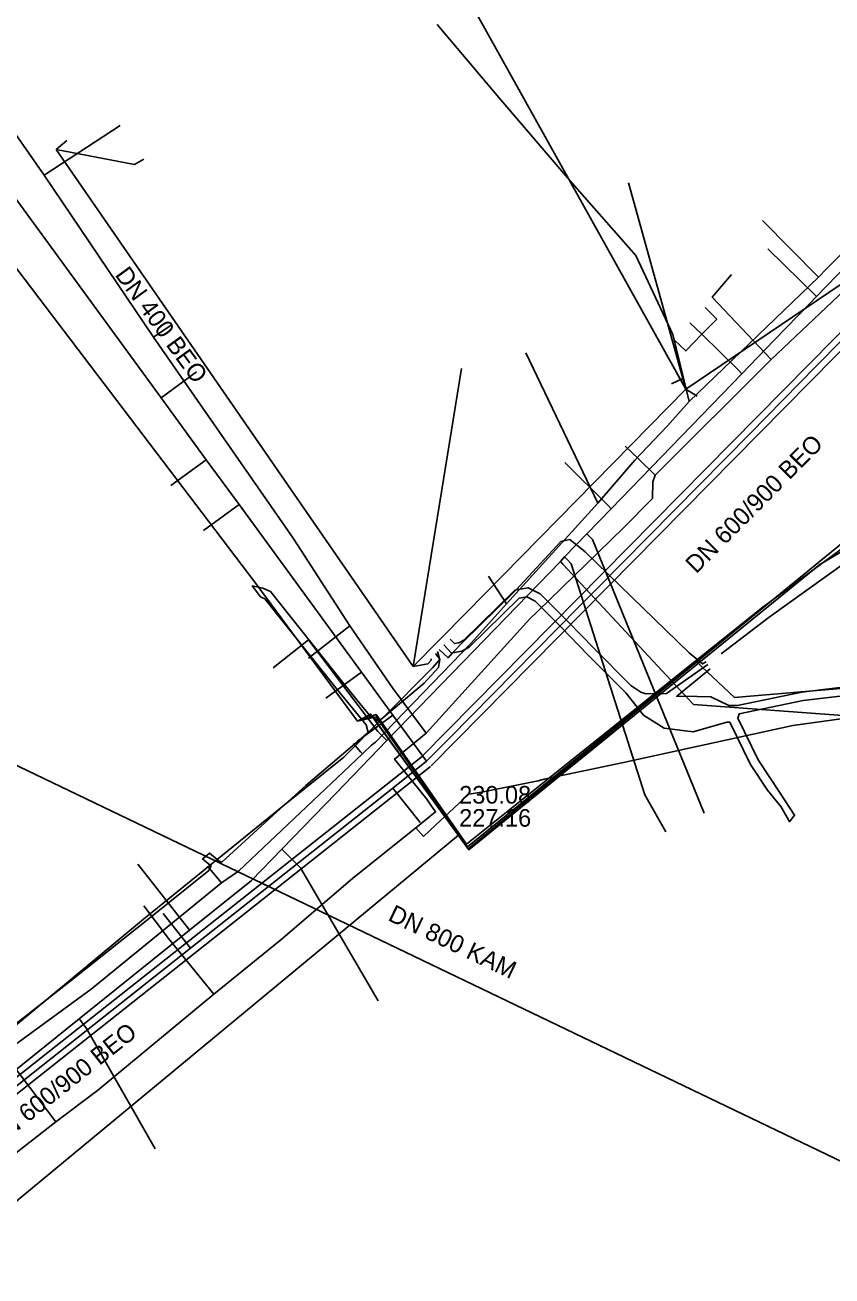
# Model space of a CAD drawing. Extents: x -598233 to -596890, y -1157848 to -1156431.
# Drawn here: x -597360.2 to -597323.5, y -1157480.1 to -1157423.2 of the extents above; entities that cross this region are included whole.
import ezdxf

# ---------------------------------------------------------------- set-up
doc = ezdxf.new("R2010")
doc.units = 0
for name, color, linetype in [('Vrstva 10', 7, 'Continuous'), ('Vrstva 12', 7, 'Continuous'), ('Vrstva 13', 7, 'Continuous'), ('Vrstva 16', 7, 'Continuous'), ('Vrstva 42', 7, 'Continuous'), ('Vrstva 5', 7, 'Continuous'), ('Vrstva 51', 7, 'Continuous'), ('Vrstva 55', 7, 'Continuous'), ('Vrstva 8', 7, 'Continuous'), ('Vrstva 9', 7, 'Continuous')]:
    doc.layers.add(name, color=color, linetype=linetype)

msp = doc.modelspace()

# ---------------------------------------------------------------- linework, layer by layer
at = {"layer": 'Vrstva 10'}
for p, q in [((-597310.498, -1157424.423), (-597342.123, -1157456.459)), ((-597310.072, -1157424.845), (-597341.697, -1157456.881)), ((-597342.096, -1157456.435), (-597369.306, -1157477.955)), ((-597341.724, -1157456.905), (-597368.934, -1157478.425))]:
    msp.add_line(p, q, dxfattribs=at)
at = {"layer": 'Vrstva 12'}
for points in [[(-597330.23, -1157439.26), (-597330.72, -1157437.28), (-597332.4, -1157433.7), (-597335.4, -1157430.29), (-597338.63, -1157426.52), (-597341.43, -1157423.19)], [(-597319.51, -1157430.1), (-597323.71, -1157434.28)], [(-597324.09, -1157434.67), (-597326.64, -1157432.1)], [(-597323.71, -1157434.28), (-597324.09, -1157434.67)], [(-597324.09, -1157434.67), (-597329.97, -1157440.32)], [(-597334.13, -1157444.94), (-597337.4, -1157438.12)], [(-597330.23, -1157439.26), (-597330.78, -1157439.53)], [(-597329.97, -1157440.32), (-597330.23, -1157439.26)], [(-597330.96, -1157441.43), (-597329.97, -1157440.32)], [(-597332.444, -1157442.995), (-597330.96, -1157441.43)], [(-597334.13, -1157444.94), (-597332.444, -1157442.995)], [(-597338.28, -1157449.52), (-597334.13, -1157444.94)], [(-597338.28, -1157449.52), (-597339.1, -1157448.26)], [(-597338.28, -1157449.52), (-597339.9, -1157451.32), (-597344.23, -1157455.8), (-597344.41, -1157455.94), (-597344.827, -1157456.334)], [(-597345.231, -1157455.857), (-597344.908, -1157456.239)], [(-597344.827, -1157456.334), (-597350.46, -1157461.66), (-597351.23, -1157462.2)], [(-597344.908, -1157456.239), (-597344.827, -1157456.334)], [(-597351.87, -1157461.44), (-597351.23, -1157462.2)], [(-597351.23, -1157462.2), (-597357.15, -1157467.03), (-597364.7, -1157472.52), (-597368.65, -1157472.25)]]:
    msp.add_lwpolyline(points, dxfattribs=at)
at = {"layer": 'Vrstva 13'}
for p, q in [((-597324.184, -1157435.56), (-597326.391, -1157433.388)), ((-597329.389, -1157437.271), (-597329.949, -1157436.747))]:
    msp.add_line(p, q, dxfattribs=at)
for points in [[(-597369.084, -1157476.741), (-597368.642, -1157476.505), (-597366.177, -1157475.18), (-597361.299, -1157471.264), (-597357.701, -1157468.374), (-597352.678, -1157464.341), (-597349.869, -1157462.086), (-597348.493, -1157460.667), (-597346.035, -1157458.129), (-597343.711, -1157455.728), (-597335.826, -1157447.593), (-597335.732, -1157447.484), (-597335.631, -1157447.387), (-597334.618, -1157446.341), (-597333.514, -1157445.198), (-597327.573, -1157439.062), (-597326.106, -1157437.545), (-597324.482, -1157435.867), (-597324.184, -1157435.56), (-597317.169, -1157428.318)], [(-597329.389, -1157437.271), (-597328.72, -1157436.584), (-597329.244, -1157436.059)], [(-597327.573, -1157439.062), (-597327.725, -1157438.906), (-597329.389, -1157437.271), (-597330.13, -1157438.031), (-597330.636, -1157437.542)], [(-597333.514, -1157445.198), (-597333.676, -1157445.038), (-597335.625, -1157443.096)], [(-597334.618, -1157446.341), (-597334.525, -1157446.434), (-597334.364, -1157446.599), (-597329.287, -1157459.032)], [(-597335.826, -1157447.593), (-597335.712, -1157447.716), (-597329.77, -1157454.09), (-597313.53, -1157455.291), (-597313.416, -1157455.302)], [(-597335.631, -1157447.387), (-597335.51, -1157447.511), (-597335.331, -1157447.699), (-597331.986, -1157458.2), (-597331.029, -1157459.87)], [(-597343.711, -1157455.728), (-597344.119, -1157455.324), (-597347.269, -1157451.15), (-597348.887, -1157452.432)], [(-597348.493, -1157460.667), (-597347.638, -1157461.509), (-597344.104, -1157467.556)], [(-597352.678, -1157464.341), (-597352.71, -1157464.298), (-597355.032, -1157461.342)], [(-597357.701, -1157468.374), (-597357.624, -1157468.471), (-597357.362, -1157468.807), (-597354.24, -1157474.273)]]:
    msp.add_lwpolyline(points, dxfattribs=at)
at = {"layer": 'Vrstva 16'}
for points in [[(-597341.93, -1157455.39), (-597343.45, -1157453.33), (-597345.39, -1157450.52), (-597347.97, -1157446.54), (-597354.32, -1157437.41), (-597359.29, -1157430.05), (-597361.27, -1157427.19), (-597363.32, -1157424.35), (-597364.28, -1157422.91), (-597364.82, -1157422.19)], [(-597359.29, -1157430.05), (-597355.83, -1157427.79)], [(-597321.25, -1157433.69), (-597326.24, -1157438.41), (-597331.51, -1157443.67), (-597331.63, -1157443.98), (-597331.64, -1157444.73), (-597332.97, -1157446.08), (-597336.301, -1157449.317), (-597336.853, -1157449.853), (-597337.21, -1157450.2), (-597341.93, -1157455.39), (-597343.36, -1157456.57), (-597343.17, -1157456.82), (-597341.9, -1157458.4), (-597341.71, -1157458.67), (-597341.5, -1157458.97), (-597342.4, -1157459.69), (-597344.95, -1157461.74), (-597345.28, -1157462), (-597348.53, -1157464.79), (-597351.58, -1157467.25), (-597356.86, -1157471.63), (-597358.76, -1157473.05), (-597362.86, -1157476.25)], [(-597326.24, -1157438.41), (-597328.92, -1157435.58), (-597328.05, -1157434.56)], [(-597354.32, -1157437.41), (-597353.47, -1157436.83)], [(-597331.51, -1157443.67), (-597332.28, -1157442.934), (-597332.88, -1157442.36)], [(-597272.69, -1157446.34), (-597275.11, -1157447.64), (-597280.67, -1157450.58), (-597288.04, -1157452.33), (-597289.5, -1157452.67), (-597291.55, -1157453.16), (-597291.94, -1157453.25), (-597294.48, -1157453.81), (-597296.79, -1157454.3), (-597301.59, -1157454.42), (-597315.52, -1157453.69), (-597321.47, -1157454.52), (-597322.95, -1157454.73), (-597325.26, -1157455.05), (-597330.05, -1157456.09), (-597332.95, -1157456.72), (-597336.56, -1157457.48), (-597336.83, -1157457.56), (-597339.41, -1157458.08), (-597339.98, -1157458.17), (-597340.87, -1157458.98), (-597341.49, -1157459.56), (-597342.05, -1157460.09)], [(-597345.39, -1157450.52), (-597347.28, -1157451.99)], [(-597342.4, -1157459.69), (-597342.05, -1157460.09)], [(-597353.64, -1157464.72), (-597354.76, -1157463.24)], [(-597353.64, -1157464.72), (-597351.58, -1157467.25)], [(-597361.89, -1157468.93), (-597358.76, -1157473.05)]]:
    msp.add_lwpolyline(points, dxfattribs=at)
at = {"layer": 'Vrstva 42'}
for points in [[(-597328.516, -1157451.786), (-597326.342, -1157450.125), (-597317.673, -1157443.91), (-597308.401, -1157436.79), (-597303.457, -1157432.614), (-597301.289, -1157431.125), (-597300.967, -1157431.396), (-597300.814, -1157431.272), (-597300.657, -1157431.145), (-597300.754, -1157430.604), (-597294.534, -1157425.309), (-597284.648, -1157417.411), (-597284.213, -1157417.708), (-597284.054, -1157417.569), (-597284.114, -1157416.887), (-597277.656, -1157411.658), (-597273.95, -1157408.774)], [(-597341.33, -1157451.598), (-597340.93, -1157451.97), (-597340.722, -1157451.747), (-597340.25, -1157451.24), (-597337.95, -1157449), (-597337.842, -1157448.883), (-597335.8, -1157446.68), (-597335.4, -1157446.6), (-597334.7, -1157447.15), (-597329.97, -1157451.74), (-597329.37, -1157452.25), (-597329.205, -1157452.152)], [(-597351.886, -1157460.944), (-597351.768, -1157460.85), (-597351.427, -1157461.136), (-597351.335, -1157461.213), (-597351.221, -1157461.254), (-597348.359, -1157458.655), (-597347.389, -1157457.774), (-597344.567, -1157455.369), (-597344.654, -1157455.023), (-597345.97, -1157453.414), (-597349.263, -1157449.286), (-597349.452, -1157449.198), (-597349.723, -1157448.839)], [(-597344.878, -1157454.117), (-597345.658, -1157453.162), (-597349.009, -1157448.964), (-597349.346, -1157448.805), (-597349.828, -1157448.701), (-597349.723, -1157448.839)], [(-597340.834, -1157451.118), (-597340.64, -1157451.324), (-597340.445, -1157451.288), (-597340.212, -1157451.163), (-597337.895, -1157448.892), (-597337.842, -1157448.883), (-597337.293, -1157448.79), (-597336.739, -1157449.062), (-597335.474, -1157450.33), (-597334.303, -1157451.535), (-597332.626, -1157453.224), (-597332.165, -1157453.534), (-597331.942, -1157453.603), (-597330.998, -1157453.596), (-597329.125, -1157452.276)], [(-597322.333, -1157453.619), (-597324.793, -1157453.917), (-597327.695, -1157454.519), (-597327.761, -1157454.718), (-597326.84, -1157456.611), (-597325.84, -1157458.113), (-597325.183, -1157459.116), (-597325.405, -1157459.422), (-597325.457, -1157459.332), (-597325.804, -1157458.725), (-597326.404, -1157457.988), (-597327.188, -1157456.811), (-597328.118, -1157454.898), (-597328.257, -1157454.89), (-597329.791, -1157455.335), (-597331.114, -1157455.172), (-597332.046, -1157454.574), (-597332.85, -1157453.566), (-597334.589, -1157451.815), (-597335.76, -1157450.61), (-597336.975, -1157449.392), (-597337.353, -1157449.206), (-597337.705, -1157449.266), (-597339.972, -1157451.489), (-597340.311, -1157451.67), (-597340.722, -1157451.747), (-597340.777, -1157451.757), (-597341.118, -1157451.379)], [(-597362.63, -1157470.36), (-597359.169, -1157467.489), (-597354.77, -1157463.84), (-597351.744, -1157461.393), (-597351.427, -1157461.136), (-597348.359, -1157458.655), (-597345.67, -1157456.48), (-597343.901, -1157454.702), (-597341.64, -1157452.43), (-597341.312, -1157452.053), (-597341.31, -1157452.05), (-597341.311, -1157452.046), (-597341.32, -1157452.018), (-597341.418, -1157451.688)], [(-597341.509, -1157451.779), (-597341.32, -1157452.018), (-597341.309, -1157452.031), (-597341.311, -1157452.046), (-597341.312, -1157452.053), (-597341.369, -1157452.415), (-597342.01, -1157453.126), (-597343.901, -1157454.702), (-597344.07, -1157454.843), (-597344.487, -1157454.595), (-597344.878, -1157454.117)], [(-597342.51, -1157452.37), (-597341.849, -1157452.25), (-597341.705, -1157452.084), (-597341.694, -1157452.012)], [(-597322.387, -1157453.233), (-597324.857, -1157453.531), (-597327.777, -1157454.137), (-597328.166, -1157454.13), (-597328.994, -1157453.748), (-597329.603, -1157453.725), (-597330.534, -1157453.718), (-597329.01, -1157452.465)], [(-597351.886, -1157460.944), (-597352.087, -1157461.105), (-597351.744, -1157461.393), (-597351.701, -1157461.429), (-597351.801, -1157461.629), (-597354.5, -1157463.805), (-597358.053, -1157466.615), (-597359.169, -1157467.489), (-597361.942, -1157469.661)]]:
    msp.add_lwpolyline(points, dxfattribs=at)
at = {"layer": 'Vrstva 5'}
msp.add_lwpolyline([(-597372.703, -1157451.027), (-597323.709, -1157474.543), (-597285.228, -1157493.013), (-597283.451, -1157493.866)], dxfattribs=at)
at = {"layer": 'Vrstva 51'}
for points in [[(-597330.13, -1157439.77), (-597341.25, -1157419.8), (-597340.8, -1157419.44)], [(-597305.25, -1157422.96), (-597330.13, -1157439.77)], [(-597358.74, -1157428.87), (-597358.259, -1157428.472)], [(-597358.74, -1157428.87), (-597355.18, -1157429.56), (-597354.76, -1157429.31)], [(-597342.51, -1157452.37), (-597358.74, -1157428.87)], [(-597330.13, -1157439.77), (-597332.73, -1157430.39)], [(-597342.51, -1157452.37), (-597340.32, -1157438.82)], [(-597330.13, -1157439.77), (-597340.091, -1157449.908), (-597342.51, -1157452.37)], [(-597330.13, -1157439.77), (-597329.611, -1157440.087)]]:
    msp.add_lwpolyline(points, dxfattribs=at)
at = {"layer": 'Vrstva 55'}
for points in [[(-597345.05, -1157454.85), (-597344.38, -1157454.64), (-597340.02, -1157460.65), (-597322.67, -1157446.47), (-597310.5, -1157437.5), (-597302.87, -1157431.81), (-597297.83, -1157427.73), (-597307.14, -1157421.07), (-597305.47, -1157418.015), (-597301.953, -1157412.621), (-597290.05, -1157383.55), (-597288.412, -1157376.549), (-597277.94, -1157351.2)], [(-597345.05, -1157454.85), (-597344.2, -1157454.54), (-597340.09, -1157460.44), (-597326.68, -1157449.71), (-597312.91, -1157439.52), (-597306.29, -1157434.51), (-597314.52, -1157424.86), (-597312.37, -1157421.82), (-597313.575, -1157419.177), (-597318.483, -1157414.201), (-597318.622, -1157414.381), (-597318.483, -1157414.201), (-597325.96, -1157406.62), (-597343.105, -1157390.75), (-597348.49, -1157384.81), (-597361.371, -1157372.543), (-597375.078, -1157358.836), (-597378, -1157358.16), (-597381.39, -1157359.59), (-597383.468, -1157361.845), (-597383.531, -1157361.997), (-597383.052, -1157362.213)], [(-597345.05, -1157454.85), (-597344.37, -1157454.64), (-597339.99, -1157460.69), (-597324.04, -1157447.73), (-597320.07, -1157445.38), (-597319.59, -1157446.67), (-597319.99, -1157445.38), (-597301.84, -1157431.2), (-597294.62, -1157425.6), (-597294.54, -1157426.01), (-597294.71, -1157425.52), (-597276.88, -1157411.34), (-597276.79, -1157411.66), (-597277.04, -1157411.34), (-597262.21, -1157399.26), (-597261.88, -1157399.67), (-597262.13, -1157399.26), (-597250.37, -1157389.62), (-597248.83, -1157389.86), (-597245.02, -1157386.21), (-597243.57, -1157383.54)], [(-597345.05, -1157454.85), (-597349.72, -1157448.54), (-597373.57, -1157417.14), (-597379.05, -1157409.73), (-597389.11, -1157394.5)], [(-597345.05, -1157454.85), (-597344.2, -1157454.65), (-597340.04, -1157460.56), (-597329.66, -1157452.14), (-597327.91, -1157453.78), (-597313.8, -1157452.58), (-597307.794, -1157452.402), (-597302.32, -1157452.8), (-597297.95, -1157453.78), (-597288.99, -1157451.92), (-597285.38, -1157450.94), (-597275.87, -1157445.58), (-597269.63, -1157442.08), (-597265.92, -1157440.66), (-597255.42, -1157436.51), (-597247.33, -1157433.55), (-597242.36, -1157430.14)], [(-597395.024, -1157502.25), (-597397, -1157498.33), (-597395.39, -1157497.25), (-597390.186, -1157494.834), (-597369.43, -1157482.54), (-597362.65, -1157478.39), (-597340.453, -1157460.03), (-597344.45, -1157454.53), (-597345.05, -1157454.85)]]:
    msp.add_lwpolyline(points, dxfattribs=at)
at = {"layer": 'Vrstva 9'}
for p, q in [((-597352.361, -1157438.979), (-597353.976, -1157440.159)), ((-597353.538, -1157444.149), (-597351.923, -1157442.969)), ((-597352.044, -1157446.191), (-597350.43, -1157445.011)), ((-597346.487, -1157453.797), (-597344.872, -1157452.617)), ((-597345.053, -1157455.759), (-597343.438, -1157454.579)), ((-597342.206, -1157459.454), (-597343.447, -1157457.886)), ((-597353.881, -1157463.587), (-597352.64, -1157465.156))]:
    msp.add_line(p, q, dxfattribs=at)
for points in [[(-597310.285, -1157424.634), (-597324.192, -1157438.722), (-597327.206, -1157441.775), (-597334.14, -1157448.799), (-597334.969, -1157449.639), (-597340.856, -1157455.603), (-597341.067, -1157455.816), (-597341.91, -1157456.67)], [(-597363, -1157427.81), (-597353.976, -1157440.159), (-597351.923, -1157442.969), (-597350.43, -1157445.011), (-597344.872, -1157452.617), (-597343.438, -1157454.579), (-597341.91, -1157456.67)], [(-597341.91, -1157456.67), (-597343.447, -1157457.886), (-597352.64, -1157465.156), (-597365.354, -1157475.212), (-597366.342, -1157475.993), (-597367.636, -1157477.017), (-597369.12, -1157478.19)]]:
    msp.add_lwpolyline(points, dxfattribs=at)

# ---------------------------------------------------------------- texts
at = {"layer": 'Vrstva 12'}
for s, rotation, p in [('DN 400 BEO', 306.1314, (-597356.099, -1157434.576)), ('DN 600/900 BEO', 45.2064, (-597329.652, -1157448.18)), ('DN 600/900 BEO', 38.3882, (-597361.484, -1157474.25))]:
    msp.add_text(s, height=0.8, rotation=rotation, dxfattribs=at).set_placement(p)
for s, p in [('230.08', (-597340.426, -1157458.594)), ('227.16', (-597340.426, -1157459.644))]:
    msp.add_text(s, height=0.8, dxfattribs=at).set_placement(p)
at = {"layer": 'Vrstva 8'}
msp.add_text('DN 800 KAM', height=0.8, rotation=334.3782, dxfattribs=at).set_placement((-597343.708, -1157463.88))

doc.saveas('drawing.dxf')
